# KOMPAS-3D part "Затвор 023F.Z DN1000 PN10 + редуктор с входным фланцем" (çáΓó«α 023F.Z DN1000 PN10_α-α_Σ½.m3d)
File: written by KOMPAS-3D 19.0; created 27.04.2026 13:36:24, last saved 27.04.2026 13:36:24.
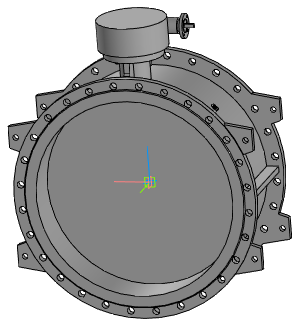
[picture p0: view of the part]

Document properties: Полное имя файла: ..\..\Затвор 023F.Z DN200-DN1600_редуктор с входным фланцем\Затвор 023F.Z DN1000 PN10 + редуктор с входным фланцем.a3d

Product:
- Part/product: Затвор 023F.Z DN1000 PN10 + редуктор с входным фланцем
    Масса: 1311.83

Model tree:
1. Операция без истории:1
